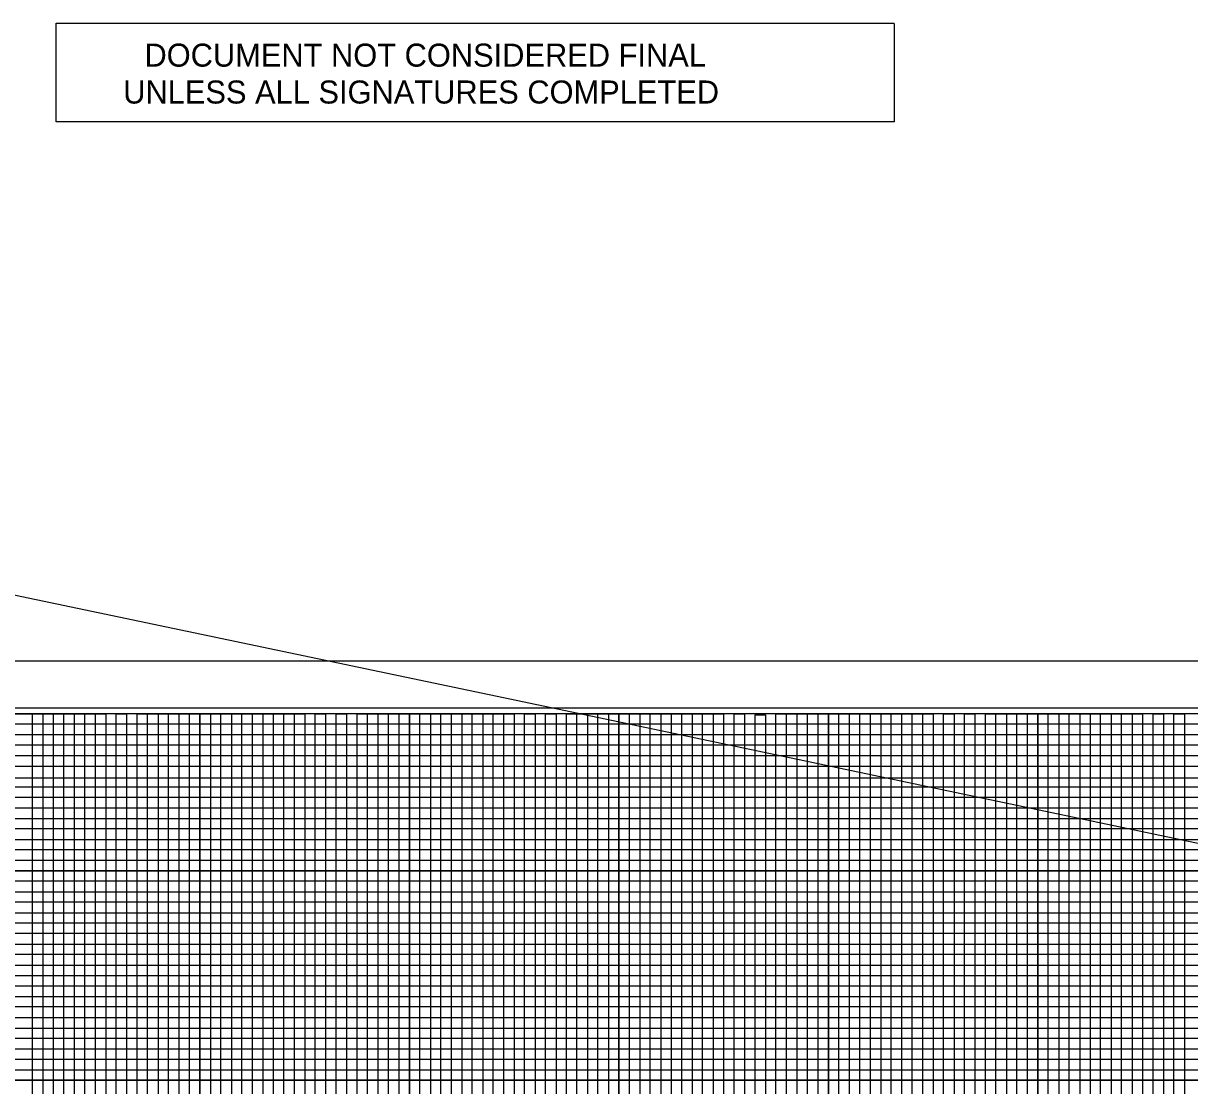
# Model space of a CAD drawing. Extents: x 1633303 to 1635397, y 883210 to 885302.
# Drawn here: x 1634280 to 1634836, y 884795 to 885302 of the extents above; entities that cross this region are included whole.
import ezdxf

# ---------------------------------------------------------------- set-up
doc = ezdxf.new("R2010")
doc.units = 0
for name, color, linetype in [('Scratch_Level_8', 7, 'Continuous'), ('Sheet Cutting Line CELL', 7, 'Continuous'), ('Sheet DOT Grid CELL', 7, 'Continuous'), ('Sheet Plot Border Inside CELL', 7, 'Continuous'), ('Sheet Plot Border Outside CELL', 7, 'Continuous'), ('Sheet Profile CELL', 7, 'Continuous'), ('Sheet Profile Grid Major CELL', 7, 'Continuous'), ('Sheet Profile Grid Middle CELL', 7, 'Continuous'), ('Sheet Profile Grid Minor CELL', 7, 'Continuous'), ('Sheet Sticker Exception Certification CELL', 7, 'Continuous'), ('Stewart Plot Border Xerox6279 and LJ5000', 7, 'Continuous')]:
    doc.layers.add(name, color=color, linetype=linetype)

msp = doc.modelspace()

# ---------------------------------------------------------------- linework, layer by layer
at = {"layer": 'Scratch_Level_8'}
msp.add_lwpolyline([(1634013.86, 883947.61), (1634013.86, 885084.12), (1635313.86, 884811.56), (1635263.86, 884541.53), (1635263.86, 883947.61)], close=True, dxfattribs=at)
at = {"layer": 'Sheet Cutting Line CELL'}
msp.add_line((1635380.86, 884997.61), (1633696.86, 884997.61), dxfattribs=at)
at = {"layer": 'Sheet DOT Grid CELL'}
for p, q in [((1634313.86, 884972.61), (1634313.86, 883947.61)), ((1634363.86, 884972.61), (1634363.86, 883947.61)), ((1634413.86, 884972.61), (1634413.86, 883947.61)), ((1634463.86, 884972.61), (1634463.86, 883947.61)), ((1634513.86, 884972.61), (1634513.86, 883947.61)), ((1634563.86, 884972.61), (1634563.86, 883947.61)), ((1634613.86, 884972.61), (1634613.86, 883947.61)), ((1634663.86, 884972.61), (1634663.86, 883947.61)), ((1634713.86, 884972.61), (1634713.86, 883947.61)), ((1634763.86, 884972.61), (1634763.86, 883947.61)), ((1634813.86, 884972.61), (1634813.86, 883947.61)), ((1633863.86, 884947.61), (1635163.81, 884947.61)), ((1633863.86, 884897.61), (1635163.81, 884897.61)), ((1633863.86, 884847.61), (1635163.81, 884847.61)), ((1633863.86, 884797.61), (1635163.81, 884797.61))]:
    msp.add_line(p, q, dxfattribs=at)
at = {"layer": 'Sheet Plot Border Inside CELL'}
msp.add_lwpolyline([(1635376.36, 884975.16), (1633709.86, 884975.16), (1633709.86, 883920.06), (1635376.36, 883920.06)], close=True, dxfattribs=at)
at = {"layer": 'Sheet Plot Border Outside CELL'}
msp.add_lwpolyline([(1635380.86, 884997.61), (1633696.86, 884997.61), (1633696.86, 883897.61), (1635380.86, 883897.61)], close=True, dxfattribs=at)
at = {"layer": 'Sheet Profile CELL'}
msp.add_lwpolyline([(1635363.86, 884972.61), (1633863.86, 884972.61), (1633863.86, 883922.61), (1635363.86, 883922.61)], close=True, dxfattribs=at)
at = {"layer": 'Sheet Profile Grid Major CELL'}
for points in [[(1634263.86, 884972.61), (1634313.86, 884972.61), (1634313.86, 883947.61)], [(1634363.86, 883947.61), (1634363.86, 884972.61), (1634413.86, 884972.61), (1634413.86, 883947.61)], [(1634463.86, 883947.61), (1634463.86, 884972.61), (1634513.86, 884972.61), (1634513.86, 883947.61)], [(1634563.86, 883947.61), (1634563.86, 884972.61), (1634613.86, 884972.61), (1634613.86, 883947.61)], [(1634663.86, 883947.61), (1634663.86, 884972.61), (1634713.86, 884972.61), (1634713.86, 883947.61)], [(1634763.86, 883947.61), (1634763.86, 884972.61), (1634813.86, 884972.61), (1634813.86, 883947.61)], [(1635163.81, 884897.61), (1633863.96, 884897.61), (1633863.96, 884947.56), (1635163.81, 884947.56)], [(1635163.81, 884797.61), (1633863.86, 884797.61), (1633863.86, 884847.61), (1635163.81, 884847.61)]]:
    msp.add_lwpolyline(points, dxfattribs=at)
at = {"layer": 'Sheet Profile Grid Middle CELL'}
for points in [[(1634238.86, 884972.61), (1634288.86, 884972.61), (1634288.86, 883947.61)], [(1634338.86, 883947.61), (1634338.86, 884972.61), (1634388.86, 884972.61), (1634388.86, 883947.61)], [(1634438.86, 883947.61), (1634438.86, 884972.61), (1634488.86, 884972.61), (1634488.86, 883947.61)], [(1634538.86, 883947.61), (1634538.86, 884972.61), (1634588.86, 884972.61), (1634588.86, 883947.61)], [(1634638.86, 883947.61), (1634638.86, 884972.61), (1634688.86, 884972.61), (1634688.86, 883947.61)], [(1634738.86, 883947.61), (1634738.86, 884972.61), (1634788.86, 884972.61), (1634788.86, 883947.61)], [(1633863.86, 884922.61), (1635163.81, 884922.61)], [(1635163.81, 884872.61), (1633863.86, 884872.61), (1633863.86, 884822.56), (1635163.81, 884822.56)]]:
    msp.add_lwpolyline(points, dxfattribs=at)
at = {"layer": 'Sheet Profile Grid Minor CELL'}
for points in [[(1635163.81, 884967.61), (1633913.86, 884967.61), (1633913.86, 884962.61), (1635163.81, 884962.61)], [(1634283.86, 883947.61), (1634283.86, 884972.61), (1634293.86, 884972.61), (1634293.86, 883947.61)], [(1634298.86, 883947.61), (1634298.86, 884972.61), (1634303.86, 884972.61), (1634303.86, 883947.61)], [(1634308.86, 883947.61), (1634308.86, 884972.61), (1634318.86, 884972.61), (1634318.86, 883947.61)], [(1634323.86, 883947.61), (1634323.86, 884972.61), (1634328.86, 884972.61), (1634328.86, 883947.61)], [(1634333.86, 883947.61), (1634333.86, 884972.61), (1634343.86, 884972.61), (1634343.86, 883947.61)], [(1634348.86, 883947.61), (1634348.86, 884972.61), (1634353.86, 884972.61), (1634353.86, 883947.61)], [(1634358.86, 883947.61), (1634358.86, 884972.61), (1634368.86, 884972.61), (1634368.86, 883947.61)], [(1634373.86, 883947.61), (1634373.86, 884972.61), (1634378.86, 884972.61), (1634378.86, 883947.61)], [(1634383.86, 883947.61), (1634383.86, 884972.61), (1634393.86, 884972.61), (1634393.86, 883947.61)], [(1634398.86, 884972.61), (1634398.86, 883947.61), (1634403.86, 883947.61), (1634403.86, 884972.61), (1634408.86, 884972.61), (1634408.86, 883947.61), (1634418.86, 883947.61), (1634418.86, 884972.61), (1634423.86, 884972.61), (1634423.86, 883947.61), (1634428.86, 883947.61), (1634428.86, 884972.61), (1634433.86, 884972.61), (1634433.86, 883947.61)], [(1634443.86, 883947.61), (1634443.86, 884972.61), (1634448.86, 884972.61), (1634448.86, 883947.61)], [(1634453.86, 883947.61), (1634453.86, 884972.61), (1634458.86, 884972.61), (1634458.86, 883947.61)], [(1634468.86, 883947.61), (1634468.86, 884972.61), (1634473.86, 884972.61), (1634473.86, 883947.61)], [(1634478.86, 883947.61), (1634478.86, 884972.61), (1634483.86, 884972.61), (1634483.86, 883947.61)], [(1634493.86, 883947.61), (1634493.86, 884972.61), (1634498.86, 884972.61), (1634498.86, 883947.61)], [(1634503.86, 883947.61), (1634503.86, 884972.61), (1634508.86, 884972.61), (1634508.86, 883947.61)], [(1634518.86, 883947.61), (1634518.86, 884972.61), (1634523.86, 884972.61), (1634523.86, 883947.61)], [(1634528.86, 883947.61), (1634528.86, 884972.61), (1634533.86, 884972.61), (1634533.86, 883947.61)], [(1634543.86, 883947.61), (1634543.86, 884972.61), (1634548.86, 884972.61), (1634548.86, 883947.61)], [(1634553.86, 883947.61), (1634553.86, 884972.61), (1634558.86, 884972.61), (1634558.86, 883947.61)], [(1634568.86, 883947.61), (1634568.86, 884972.61), (1634573.86, 884972.61), (1634573.86, 883947.61)], [(1634578.86, 883947.61), (1634578.86, 884972.61), (1634583.86, 884972.61), (1634583.86, 883947.61)], [(1634593.86, 883947.61), (1634593.86, 884972.61), (1634598.86, 884972.61), (1634598.86, 883947.61)], [(1634603.86, 883947.61), (1634603.86, 884972.61), (1634608.86, 884972.61), (1634608.86, 883947.61)], [(1634618.86, 883947.61), (1634618.86, 884972.61), (1634623.86, 884972.61), (1634623.86, 883947.61)], [(1634628.86, 883947.61), (1634628.86, 884972.01), (1634633.86, 884972.01), (1634633.86, 883947.61)], [(1634643.86, 883947.61), (1634643.86, 884972.61), (1634648.86, 884972.61), (1634648.86, 883947.61)], [(1634653.86, 883947.61), (1634653.86, 884972.61), (1634658.86, 884972.61), (1634658.86, 883947.61)], [(1634668.86, 883947.61), (1634668.86, 884972.61), (1634673.86, 884972.61), (1634673.86, 883947.61)], [(1634678.86, 883947.61), (1634678.86, 884972.61), (1634683.86, 884972.61), (1634683.86, 883947.61)], [(1634693.86, 883947.61), (1634693.86, 884972.61), (1634698.86, 884972.61), (1634698.86, 883947.61)], [(1634703.86, 883947.61), (1634703.86, 884972.61), (1634708.86, 884972.61), (1634708.86, 883947.61)], [(1634718.86, 883947.61), (1634718.86, 884972.61), (1634723.86, 884972.61), (1634723.86, 883947.61)], [(1634728.86, 883947.61), (1634728.86, 884972.61), (1634733.86, 884972.61), (1634733.86, 883947.61)], [(1634743.86, 883947.61), (1634743.86, 884972.61), (1634748.86, 884972.61), (1634748.86, 883947.61)], [(1634753.86, 883947.61), (1634753.86, 884972.61), (1634758.86, 884972.61), (1634758.86, 883947.61)], [(1634768.86, 883947.61), (1634768.86, 884972.61), (1634773.86, 884972.61), (1634773.86, 883947.61)], [(1634778.86, 883947.61), (1634778.86, 884972.61), (1634783.86, 884972.61), (1634783.86, 883947.61)], [(1634793.86, 883947.61), (1634793.86, 884972.61), (1634798.86, 884972.61), (1634798.86, 883947.61)], [(1634803.86, 883947.61), (1634803.86, 884972.61), (1634808.86, 884972.61), (1634808.86, 883947.61)], [(1634818.86, 883947.61), (1634818.86, 884972.61), (1634823.86, 884972.61), (1634823.86, 883947.61)], [(1634828.86, 883947.61), (1634828.86, 884972.61), (1634833.86, 884972.61), (1634833.86, 883947.61)], [(1635163.81, 884957.61), (1633913.86, 884957.61), (1633913.86, 884952.61), (1635163.81, 884952.61)], [(1635163.81, 884941.86), (1633914.86, 884941.86), (1633914.86, 884937.61), (1635163.81, 884937.61)], [(1635163.81, 884932.61), (1633913.86, 884932.61), (1633913.86, 884927.61), (1635163.81, 884927.61)], [(1635163.81, 884917.61), (1633913.86, 884917.61), (1633913.86, 884912.61), (1635163.81, 884912.61)], [(1635163.81, 884907.61), (1633913.86, 884907.61), (1633913.86, 884902.61), (1635163.81, 884902.61)], [(1635163.81, 884892.61), (1633913.86, 884892.61), (1633913.86, 884887.61), (1635163.81, 884887.61)], [(1635163.81, 884882.61), (1633913.86, 884882.61), (1633913.86, 884877.61), (1635163.81, 884877.61)], [(1635163.81, 884867.61), (1633913.86, 884867.61), (1633913.86, 884862.61), (1635163.81, 884862.61)], [(1635163.81, 884857.61), (1633913.86, 884857.61), (1633913.86, 884852.61), (1635163.81, 884852.61)], [(1635163.81, 884842.61), (1633913.86, 884842.61), (1633913.86, 884837.61), (1635163.81, 884837.61)], [(1635163.81, 884832.61), (1633913.86, 884832.61), (1633913.86, 884832.61), (1633913.86, 884812.61), (1635163.81, 884812.61)], [(1633913.86, 884827.61), (1635163.81, 884827.61)], [(1635163.81, 884817.61), (1633913.86, 884817.61)], [(1635163.81, 884807.61), (1633913.86, 884807.61), (1633913.86, 884802.61), (1635163.81, 884802.61)]]:
    msp.add_lwpolyline(points, dxfattribs=at)
at = {"layer": 'Sheet Sticker Exception Certification CELL'}
for p, q in [((1634295.23, 885255.12), (1634295.23, 885302.12)), ((1634295.23, 885302.12), (1634695.3, 885302.12)), ((1634695.3, 885302.09), (1634695.3, 885255.09)), ((1634695.3, 885255.12), (1634295.23, 885255.12))]:
    msp.add_line(p, q, dxfattribs=at)
at = {"layer": 'Stewart Plot Border Xerox6279 and LJ5000'}
msp.add_lwpolyline([(1633696.86, 883897.61), (1635396.86, 883897.61), (1635396.86, 884997.61), (1633696.86, 884997.61)], close=True, dxfattribs=at)

# ---------------------------------------------------------------- texts
at = {"layer": 'Sheet Sticker Exception Certification CELL'}
for s, p in [('DOCUMENT NOT CONSIDERED FINAL', (1634337.37, 885281.43)), ('UNLESS ALL SIGNATURES COMPLETED', (1634327.23, 885263.83))]:
    msp.add_text(s, height=11, rotation=0, dxfattribs=at).set_placement(p)

doc.saveas('drawing.dxf')
